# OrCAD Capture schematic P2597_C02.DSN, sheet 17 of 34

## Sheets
17 17_DSI Connector: size Custom
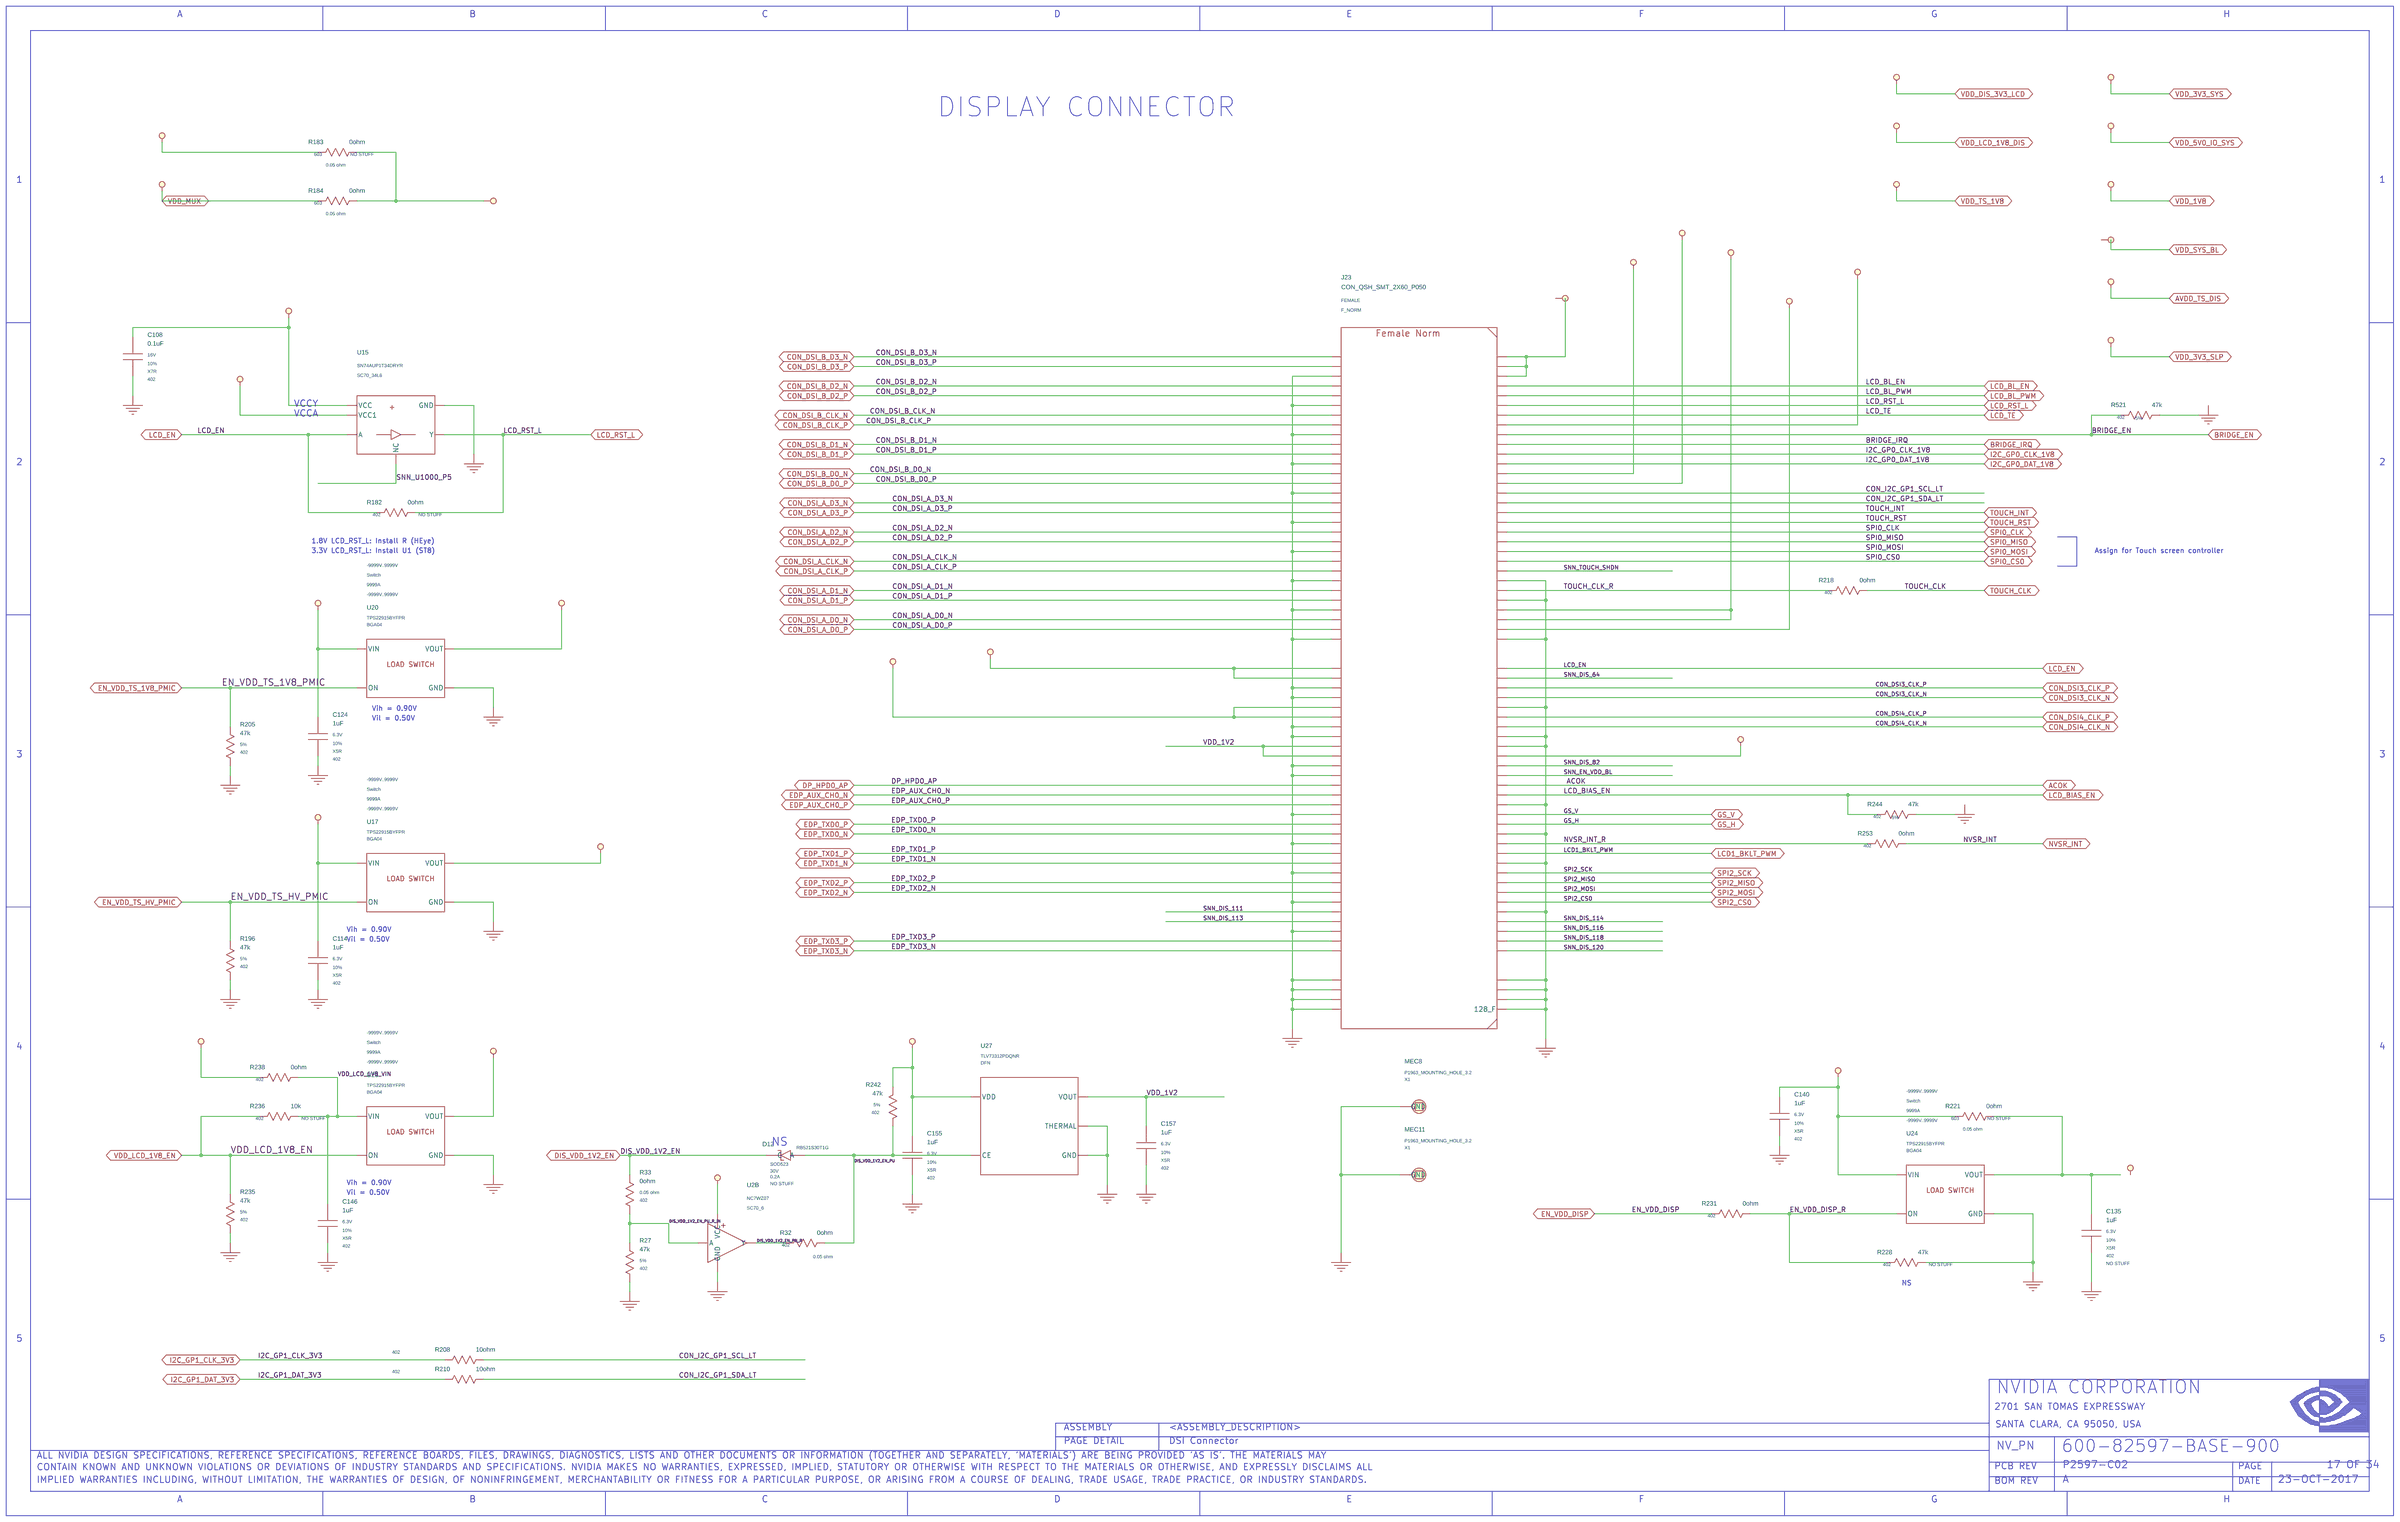
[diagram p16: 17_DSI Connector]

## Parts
sheet 17_DSI Connector
C108  0.1uF  [402]
C114  1uF  [402]
C124  1uF  [402]
C135  1uF  [402]
C140  1uF  [402]
C146  1uF  [402]
C155  1uF  [402]
C157  1uF  [402]
D12  D_SCHOTTKY  [DIODE_SMD_SOD523_B]
J23  CON_B2B_120  [CON_QSH_120_SMT_ST_P005]
MEC8  MOUNTING_HOLE  [MEC_HOLE_PTH_599C_INT422C_B701C320P]
MEC11  MOUNTING_HOLE  [MEC_HOLE_PTH_599C_INT422C_B701C320P]
R27  47k  [402]
R32  0ohm  [402]
R33  0ohm  [402]
R182  0ohm  [402]
R183  0ohm  [603]
R184  0ohm  [603]
R196  47k  [402]
R205  47k  [402]
R208  10ohm  [402]
R210  10ohm  [402]
R218  0ohm  [402]
R221  0ohm  [603]
R228  47k  [402]
R231  0ohm  [402]
R235  47k  [402]
R236  10k  [402]
R238  0ohm  [402]
R242  47k  [402]
R244  47k  [402]
R253  0ohm  [402]
R521  47k  [402]
U15  U_BUF_FXLP34  [DFN06_P050_015X010_C]
U17  U_SW_LOAD  [BGA_0004_P040_008X008]
U20  U_SW_LOAD  [BGA_0004_P040_008X008]
U24  U_SW_LOAD  [BGA_0004_P040_008X008]
U26  U_SW_LOAD  [BGA_0004_P040_008X008]
U27  0mV  [DFN04_P065_010X010_T005X005]
sheet 22_FAN AND DEBUG
U2  U_BUF_OD  [SC70_6]  (sections A,B)

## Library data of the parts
C108 = C: ASSEMBLY: DISPLAY; CDS_LIB: discrete; CDS_PART_NAME: C_0402-0.1UF,X7R,10%,16V,036-0014-000; CDS_PHYS_PART_NAME: C_0402-0.1UF,X7R,10%,16V,036-0014-000-0.1UF,036-0014-000; CDS_SEC: 1; DEVICE_TYPENAME: C_0402-01UFX7R1016V036-0014-000-01UF036-0014-000; DRAWING: @P2597_C02_LIB.P2597_C02(SCH_1):PAGE17; MAT: X7R; MAX_VOLTAGE: 16V; NV_PN: 036-0014-000; PATH: I301; PHYS_PAGE: 17; ROT: 0; SEC: 1; SIGNAL_MODEL: nv_cap; TOL: 10%; VER: 1; XY: (-11500,5800)
C114 = C: ASSEMBLY: DISPLAY; CDS_LIB: discrete; CDS_PART_NAME: C_0402-1UF,X5R,10%,6.3V,039-0008-000; CDS_PHYS_PART_NAME: C_0402-1UF,X5R,10%,6.3V,039-0008-000-039-0008-000,1UF; CDS_SEC: 1; DEVICE_TYPENAME: C_0402-1UFX5R1063V039-0008-000-039-0008-0001UF; DRAWING: @P2597_C02_LIB.P2597_C02(SCH_1):PAGE17; MAT: X5R; MAX_VOLTAGE: 6.3V; NV_PN: 039-0008-000; PATH: I336; PHYS_PAGE: 17; ROT: 0; SEC: 1; SIGNAL_MODEL: DEFAULT_CAPACITOR_1e+06pF_2_1; TOL: 10%; VER: 1; XY: (-10550,2700)
C124 = C: ASSEMBLY: DISPLAY; CDS_LIB: discrete; CDS_PART_NAME: C_0402-1UF,X5R,10%,6.3V,039-0008-000; CDS_PHYS_PART_NAME: C_0402-1UF,X5R,10%,6.3V,039-0008-000-039-0008-000,1UF; CDS_SEC: 1; DEVICE_TYPENAME: C_0402-1UFX5R1063V039-0008-000-039-0008-0001UF; DRAWING: @P2597_C02_LIB.P2597_C02(SCH_1):PAGE17; MAT: X5R; MAX_VOLTAGE: 6.3V; NV_PN: 039-0008-000; PATH: I338; PHYS_PAGE: 17; ROT: 0; SEC: 1; SIGNAL_MODEL: DEFAULT_CAPACITOR_1e+06pF_2_1; TOL: 10%; VER: 1; XY: (-10550,3850)
C135 = C: ASSEMBLY: DISPLAY; CDS_LIB: discrete; CDS_PART_NAME: C_0402-1UF,X5R,10%,6.3V,039-0008-000; CDS_PHYS_PART_NAME: C_0402-1UF,X5R,10%,6.3V,039-0008-000-039-0008-000,1UF; CDS_SEC: 1; DEVICE_TYPENAME: C_0402-1UFX5R1063V039-0008-000-039-0008-0001UF; DRAWING: @P2597_C02_LIB.P2597_C02(SCH_1):PAGE17; MAT: X5R; MAX_VOLTAGE: 6.3V; NV_PN: 039-0008-000; PATH: I233; PHYS_PAGE: 17; ROT: 0; SEC: 1; SIGNAL_MODEL: DEFAULT_CAPACITOR_1e+06pF_2_1; SKU: NO STUFF; TOL: 10%; VER: 1; XY: (-1450,1300)
C140 = C: ASSEMBLY: DISPLAY; CDS_LIB: discrete; CDS_PART_NAME: C_0402-1UF,X5R,10%,6.3V,039-0008-000; CDS_PHYS_PART_NAME: C_0402-1UF,X5R,10%,6.3V,039-0008-000-039-0008-000,1UF; CDS_SEC: 1; DEVICE_TYPENAME: C_0402-1UFX5R1063V039-0008-000-039-0008-0001UF; DRAWING: @P2597_C02_LIB.P2597_C02(SCH_1):PAGE17; MAT: X5R; MAX_VOLTAGE: 6.3V; NV_PN: 039-0008-000; PATH: I234; PHYS_PAGE: 17; ROT: 0; SEC: 1; SIGNAL_MODEL: DEFAULT_CAPACITOR_1e+06pF_2_1; TOL: 10%; VER: 1; XY: (-3050,1900)
C146 = C: ASSEMBLY: DISPLAY; CDS_LIB: discrete; CDS_PART_NAME: C_0402-1UF,X5R,10%,6.3V,039-0008-000; CDS_PHYS_PART_NAME: C_0402-1UF,X5R,10%,6.3V,039-0008-000-039-0008-000,1UF; CDS_SEC: 1; DEVICE_TYPENAME: C_0402-1UFX5R1063V039-0008-000-039-0008-0001UF; DRAWING: @P2597_C02_LIB.P2597_C02(SCH_1):PAGE17; MAT: X5R; MAX_VOLTAGE: 6.3V; NV_PN: 039-0008-000; PATH: I333; PHYS_PAGE: 17; ROT: 0; SEC: 1; SIGNAL_MODEL: DEFAULT_CAPACITOR_1e+06pF_2_1; TOL: 10%; VER: 1; XY: (-10500,1350)
C155 = C: ASSEMBLY: DISPLAY; CDS_LIB: discrete; CDS_PART_NAME: C_0402-1UF,X5R,10%,6.3V,039-0008-000; CDS_PHYS_PART_NAME: C_0402-1UF,X5R,10%,6.3V,039-0008-000-039-0008-000,1UF; CDS_SEC: 1; DEVICE_TYPENAME: C_0402-1UFX5R1063V039-0008-000-039-0008-0001UF; DRAWING: @P2597_C02_LIB.P2597_C02(SCH_1):PAGE17; MAT: X5R; MAX_VOLTAGE: 6.3V; NV_PN: 039-0008-000; PATH: I320; PHYS_PAGE: 17; ROT: 0; SEC: 1; SIGNAL_MODEL: nv_cap; TOL: 10%; VER: 1; XY: (-7500,1700)
C157 = C: ASSEMBLY: DISPLAY; CDS_LIB: discrete; CDS_PART_NAME: C_0402-1UF,X5R,10%,6.3V,039-0008-000; CDS_PHYS_PART_NAME: C_0402-1UF,X5R,10%,6.3V,039-0008-000-039-0008-000,1UF; CDS_SEC: 1; DEVICE_TYPENAME: C_0402-1UFX5R1063V039-0008-000-039-0008-0001UF; DRAWING: @P2597_C02_LIB.P2597_C02(SCH_1):PAGE17; MAT: X5R; MAX_VOLTAGE: 6.3V; NV_PN: 039-0008-000; PATH: I325; PHYS_PAGE: 17; ROT: 0; SEC: 1; SIGNAL_MODEL: nv_cap; TOL: 10%; VER: 1; XY: (-6300,1750)
D12 = D_SCHOTTKY: ASSEMBLY: DISPLAY; CDS_LIB: discrete; CDS_PART_NAME: D_SCHOTTKY_SOD523-RB521S30T1G,SINGLE,30V,1A,0.5V@0.2A,0.2A,090-0102-000; CDS_PHYS_PART_NAME: D_SCHOTTKY_SOD523-RB521S30T1G,SINGLE,30V,1A,0.5V@0.2A,0.2A,090-0102-000-090-0102-000; CDS_SEC: 1; CONFIGURATION: Single; CONTINUOUS_CURRENT: 0.2A; DEVICE_TYPENAME: D_SCHOTTKY_SOD523-RB521S30T1GSINGLE30V1A05V02A02A090-0102-000-090-0102-000; DRAWING: @P2597_C02_LIB.P2597_C02(SCH_1):PAGE17; FORWARD_VOLTAGE: 0.5V@0.2A; MAX_CURRENT: 1A; MAX_VOLTAGE: 30V; NV_NAME: RB521S30T1G; NV_PN: 090-0102-000; PACK_TYPE: SOD523; PATH: I339; PHYS_PAGE: 17; ROT: 0; SEC: 1; SEC_TYPE: SOD523; SKU: NO STUFF; VER: 1; XY: (-8150,1700)
J23 = CON_B2B_120: ANGLE: 0; ASSEMBLY: DISPLAY; CDS_LIB: electro_mechanic; CDS_PART_NAME: CON_B2B_120_F_NORM-CON_QSH_SMT_2X60_P050,FEMALE,0.5MM,0,YES,YES,NO,NO,NO,NA,NA,080-1346-000; CDS_PHYS_PART_NAME: CON_B2B_120_F_NORM-CON_QSH_SMT_2X60_P050,FEMALE,0.5MM,0,YES,YES,NO,NO,NO,NA,NA,080-1346-000-080-1346-000; CDS_SEC: 1; DEVICE_TYPENAME: CON_B2B_120_F_NORM-CON_QSH_SMT_2X60_P050FEMALE05MM0YESYESNONONONANA080-1346-000-080-1346-000; DRAWING: @P2597_C02_LIB.P2597_C02(SCH_1):PAGE17; EMI_GROUND_TAB: NO; GENDER: FEMALE; LATCHING: NO; MAX_CURRENT: NA; MAX_VOLTAGE: NA; NV_NAME: CON_QSH_SMT_2X60_P050; NV_PN: 080-1346-000; PACK_TYPE: F_NORM; PATH: I274; PHYS_PAGE: 17; PITCH: 0.5MM; REFLOW: YES; ROT: 0; SEC: 1; SEC_TYPE: F_NORM; SHIELDED: NO; SHROUDED: YES; VER: 1; XY: (-4900,4150)
MEC8 = MOUNTING_HOLE: CDS_LIB: mechanic; CDS_PART_NAME: MOUNTING_HOLE_X1-P1963_MOUNTING_HOLE_3.2; CDS_PHYS_PART_NAME: MOUNTING_HOLE_X1-P1963_MOUNTING_HOLE_3.2; CDS_SEC: 1; DEVICE_TYPENAME: MOUNTING_HOLE_X1-P1963_MOUNTING_HOLE_32; DRAWING: @P2597_C02_LIB.P2597_C02(SCH_1):PAGE17; NV_NAME: P1963_MOUNTING_HOLE_3.2; PACK_TYPE: X1; PATH: I309; PHYS_PAGE: 17; ROT: 0; SEC: 1; SEC_TYPE: X1; VER: 1; XY: (-4900,1950)
MEC11 = MOUNTING_HOLE: CDS_LIB: mechanic; CDS_PART_NAME: MOUNTING_HOLE_X1-P1963_MOUNTING_HOLE_3.2; CDS_PHYS_PART_NAME: MOUNTING_HOLE_X1-P1963_MOUNTING_HOLE_3.2; CDS_SEC: 1; DEVICE_TYPENAME: MOUNTING_HOLE_X1-P1963_MOUNTING_HOLE_32; DRAWING: @P2597_C02_LIB.P2597_C02(SCH_1):PAGE17; NV_NAME: P1963_MOUNTING_HOLE_3.2; PACK_TYPE: X1; PATH: I311; PHYS_PAGE: 17; ROT: 0; SEC: 1; SEC_TYPE: X1; VER: 1; XY: (-4900,1600)
R27 = R#1: ASSEMBLY: DISPLAY; CDS_LIB: discrete; CDS_PART_NAME: R_0402-47K,5 %,62.5MW,195-0599-000; CDS_PHYS_PART_NAME: R_0402-47K,5 %,62.5MW,195-0599-000-195-0599-000,47K; CDS_SEC: 1; CHIPS_PART_NAME: R; DEVICE_TYPENAME: R_0402-47K5625MW195-0599-000-195-0599-00047K; DRAWING: @P2597_C02_LIB.P2597_C02(SCH_1):PAGE17; MAX_WATTAGE: 62.5mW; NV_PN: 195-0599-000; PATH: I352; PHYS_PAGE: 17; ROT: 0; SEC: 1; SIGNAL_MODEL: nv_res; TOL: 5%; VER: 2; XY: (-8950,1150)
R32 = R: ASSEMBLY: DISPLAY; CDS_LIB: discrete; CDS_PART_NAME: R_0402-0OHM,0.05 OHM,62.5MW,195-2655-000; CDS_PHYS_PART_NAME: R_0402-0OHM,0.05 OHM,62.5MW,195-2655-000-0OHM,195-2655-000; CDS_SEC: 1; DEVICE_TYPENAME: R_0402-0OHM005OHM625MW195-2655-000-0OHM195-2655-000; DRAWING: @P2597_C02_LIB.P2597_C02(SCH_1):PAGE17; MAX_WATTAGE: 62.5mW; NV_PN: 195-2655-000; PATH: I359; PHYS_PAGE: 17; ROT: 0; SEC: 1; SIGNAL_MODEL: nv_res; TOL: 0.05 ohm; VER: 1; XY: (-8050,1250)
R33 = R#1: ASSEMBLY: DISPLAY; CDS_LIB: discrete; CDS_PART_NAME: R_0402-0OHM,0.05 OHM,62.5MW,195-2655-000; CDS_PHYS_PART_NAME: R_0402-0OHM,0.05 OHM,62.5MW,195-2655-000-0OHM,195-2655-000; CDS_SEC: 1; CHIPS_PART_NAME: R; DEVICE_TYPENAME: R_0402-0OHM005OHM625MW195-2655-000-0OHM195-2655-000; DRAWING: @P2597_C02_LIB.P2597_C02(SCH_1):PAGE17; MAX_WATTAGE: 62.5mW; NV_PN: 195-2655-000; PATH: I358; PHYS_PAGE: 17; ROT: 0; SEC: 1; SIGNAL_MODEL: nv_res; TOL: 0.05 ohm; VER: 2; XY: (-8950,1500)
R182 = R: ASSEMBLY: DISPLAY; CDS_LIB: discrete; CDS_PART_NAME: R_0402-0OHM,0.05 OHM,62.5MW,195-2655-000; CDS_PHYS_PART_NAME: R_0402-0OHM,0.05 OHM,62.5MW,195-2655-000-0OHM,195-2655-000; CDS_SEC: 1; DEVICE_TYPENAME: R_0402-0OHM005OHM625MW195-2655-000-0OHM195-2655-000; DRAWING: @P2597_C02_LIB.P2597_C02(SCH_1):PAGE17; MAX_WATTAGE: 62.5mW; NV_PN: 195-2655-000; PATH: I300; PHYS_PAGE: 17; ROT: 0; SEC: 1; SIGNAL_MODEL: nv_res; SKU: NO STUFF; TOL: 0.05 ohm; VER: 1; XY: (-10150,5000)
R183 = R: ASSEMBLY: DISPLAY; CDS_LIB: discrete; CDS_PART_NAME: R_0603-0OHM,0.05 OHM,0.1W,195-2656-000; CDS_PHYS_PART_NAME: R_0603-0OHM,0.05 OHM,0.1W,195-2656-000-0OHM,195-2656-000; CDS_SEC: 1; DEVICE_TYPENAME: R_0603-0OHM005OHM01W195-2656-000-0OHM195-2656-000; DRAWING: @P2597_C02_LIB.P2597_C02(SCH_1):PAGE17; MAX_WATTAGE: 0.1W; NV_PN: 195-2656-000; PATH: I137; PHYS_PAGE: 17; ROT: 0; SEC: 1; SIGNAL_MODEL: nv_res; SKU: NO STUFF; TOL: 0.05 ohm; VER: 1; XY: (-10450,6850)
R184 = R: ASSEMBLY: DISPLAY; CDS_LIB: discrete; CDS_PART_NAME: R_0603-0OHM,0.05 OHM,0.1W,195-2656-000; CDS_PHYS_PART_NAME: R_0603-0OHM,0.05 OHM,0.1W,195-2656-000-0OHM,195-2656-000; CDS_SEC: 1; DEVICE_TYPENAME: R_0603-0OHM005OHM01W195-2656-000-0OHM195-2656-000; DRAWING: @P2597_C02_LIB.P2597_C02(SCH_1):PAGE17; MAX_WATTAGE: 0.1W; NV_PN: 195-2656-000; PATH: I136; PHYS_PAGE: 17; ROT: 0; SEC: 1; SIGNAL_MODEL: nv_res; TOL: 0.05 ohm; VER: 1; XY: (-10450,6600)
R196 = R#1: ASSEMBLY: DISPLAY; CDS_LIB: discrete; CDS_PART_NAME: R_0402-47K,5 %,62.5MW,195-0599-000; CDS_PHYS_PART_NAME: R_0402-47K,5 %,62.5MW,195-0599-000-195-0599-000,47K; CDS_SEC: 1; CHIPS_PART_NAME: R; DEVICE_TYPENAME: R_0402-47K5625MW195-0599-000-195-0599-00047K; DRAWING: @P2597_C02_LIB.P2597_C02(SCH_1):PAGE17; MAX_WATTAGE: 62.5mW; NV_PN: 195-0599-000; PATH: I349; PHYS_PAGE: 17; ROT: 0; SEC: 1; SIGNAL_MODEL: nv_res; TOL: 5%; VER: 2; XY: (-11000,2700)
R205 = R#1: ASSEMBLY: DISPLAY; CDS_LIB: discrete; CDS_PART_NAME: R_0402-47K,5 %,62.5MW,195-0599-000; CDS_PHYS_PART_NAME: R_0402-47K,5 %,62.5MW,195-0599-000-195-0599-000,47K; CDS_SEC: 1; CHIPS_PART_NAME: R; DEVICE_TYPENAME: R_0402-47K5625MW195-0599-000-195-0599-00047K; DRAWING: @P2597_C02_LIB.P2597_C02(SCH_1):PAGE17; MAX_WATTAGE: 62.5mW; NV_PN: 195-0599-000; PATH: I347; PHYS_PAGE: 17; ROT: 0; SEC: 1; SIGNAL_MODEL: nv_res; TOL: 5%; VER: 2; XY: (-11000,3800)
R208 = R: ASSEMBLY: DISPLAY; CDS_LIB: discrete; CDS_PART_NAME: R_0402-10OHM,1 %,62.5MW,195-0001-000; CDS_PHYS_PART_NAME: R_0402-10OHM,1 %,62.5MW,195-0001-000-10OHM,195-0001-000; CDS_SEC: 1; DEVICE_TYPENAME: R_0402-10OHM1625MW195-0001-000-10OHM195-0001-000; DRAWING: @P2597_C02_LIB.P2597_C02(SCH_1):PAGE17; MAX_WATTAGE: 62.5mW; NV_PN: 195-0001-000; PATH: I146; PHYS_PAGE: 17; ROT: 0; SEC: 1; SIGNAL_MODEL: nv_res; TOL: 1%; VER: 1; XY: (-9800,650)
R210 = R: ASSEMBLY: DISPLAY; CDS_LIB: discrete; CDS_PART_NAME: R_0402-10OHM,1 %,62.5MW,195-0001-000; CDS_PHYS_PART_NAME: R_0402-10OHM,1 %,62.5MW,195-0001-000-10OHM,195-0001-000; CDS_SEC: 1; DEVICE_TYPENAME: R_0402-10OHM1625MW195-0001-000-10OHM195-0001-000; DRAWING: @P2597_C02_LIB.P2597_C02(SCH_1):PAGE17; MAX_WATTAGE: 62.5mW; NV_PN: 195-0001-000; PATH: I145; PHYS_PAGE: 17; ROT: 0; SEC: 1; SIGNAL_MODEL: nv_res; TOL: 1%; VER: 1; XY: (-9800,550)
R218 = R: ASSEMBLY: DISPLAY; CDS_LIB: discrete; CDS_PART_NAME: R_0402-0OHM,0.05 OHM,62.5MW,195-2655-000; CDS_PHYS_PART_NAME: R_0402-0OHM,0.05 OHM,62.5MW,195-2655-000-0OHM,195-2655-000; CDS_SEC: 1; DEVICE_TYPENAME: R_0402-0OHM005OHM625MW195-2655-000-0OHM195-2655-000; DRAWING: @P2597_C02_LIB.P2597_C02(SCH_1):PAGE17; MAX_WATTAGE: 62.5mW; NV_PN: 195-2655-000; PATH: I221; PHYS_PAGE: 17; ROT: 0; SEC: 1; SIGNAL_MODEL: nv_res; TOL: 0.05 ohm; VER: 1; XY: (-2700,4600)
R221 = R: ASSEMBLY: DISPLAY; CDS_LIB: discrete; CDS_PART_NAME: R_0603-0OHM,0.05 OHM,0.1W,195-2656-000; CDS_PHYS_PART_NAME: R_0603-0OHM,0.05 OHM,0.1W,195-2656-000-0OHM,195-2656-000; CDS_SEC: 1; DEVICE_TYPENAME: R_0603-0OHM005OHM01W195-2656-000-0OHM195-2656-000; DRAWING: @P2597_C02_LIB.P2597_C02(SCH_1):PAGE17; MAX_WATTAGE: 0.1W; NV_PN: 195-2656-000; PATH: I153; PHYS_PAGE: 17; ROT: 0; SEC: 1; SIGNAL_MODEL: nv_res; SKU: NO STUFF; TOL: 0.05 ohm; VER: 1; XY: (-2050,1900)
R228 = R: ASSEMBLY: DISPLAY; CDS_LIB: discrete; CDS_PART_NAME: R_0402-47K,5 %,62.5MW,195-0599-000; CDS_PHYS_PART_NAME: R_0402-47K,5 %,62.5MW,195-0599-000-195-0599-000,47K; CDS_SEC: 1; DEVICE_TYPENAME: R_0402-47K5625MW195-0599-000-195-0599-00047K; DRAWING: @P2597_C02_LIB.P2597_C02(SCH_1):PAGE17; MAX_WATTAGE: 62.5mW; NV_PN: 195-0599-000; PATH: I231; PHYS_PAGE: 17; ROT: 0; SEC: 1; SIGNAL_MODEL: nv_res; SKU: NO STUFF; TOL: 5%; VER: 1; XY: (-2400,1150)
R231 = R: ASSEMBLY: DISPLAY; CDS_LIB: discrete; CDS_PART_NAME: R_0402-0OHM,0.05 OHM,62.5MW,195-2655-000; CDS_PHYS_PART_NAME: R_0402-0OHM,0.05 OHM,62.5MW,195-2655-000-0OHM,195-2655-000; CDS_SEC: 1; DEVICE_TYPENAME: R_0402-0OHM005OHM625MW195-2655-000-0OHM195-2655-000; DRAWING: @P2597_C02_LIB.P2597_C02(SCH_1):PAGE17; MAX_WATTAGE: 62.5mW; NV_PN: 195-2655-000; PATH: I230; PHYS_PAGE: 17; ROT: 0; SEC: 1; SIGNAL_MODEL: nv_res; TOL: 0.05 ohm; VER: 1; XY: (-3300,1400)
R235 = R#1: ASSEMBLY: DISPLAY; CDS_LIB: discrete; CDS_PART_NAME: R_0402-47K,5 %,62.5MW,195-0599-000; CDS_PHYS_PART_NAME: R_0402-47K,5 %,62.5MW,195-0599-000-195-0599-000,47K; CDS_SEC: 1; CHIPS_PART_NAME: R; DEVICE_TYPENAME: R_0402-47K5625MW195-0599-000-195-0599-00047K; DRAWING: @P2597_C02_LIB.P2597_C02(SCH_1):PAGE17; MAX_WATTAGE: 62.5mW; NV_PN: 195-0599-000; PATH: I351; PHYS_PAGE: 17; ROT: 0; SEC: 1; SIGNAL_MODEL: nv_res; TOL: 5%; VER: 2; XY: (-11000,1400)
R236 = R: ASSEMBLY: DISPLAY; CDS_LIB: discrete; CDS_PART_NAME: R_0402-10K,5 %,62.5MW,195-0486-000; CDS_PHYS_PART_NAME: R_0402-10K,5 %,62.5MW,195-0486-000-10K,195-0486-000; CDS_SEC: 1; DEVICE_TYPENAME: R_0402-10K5625MW195-0486-000-10K195-0486-000; DRAWING: @P2597_C02_LIB.P2597_C02(SCH_1):PAGE17; MAX_WATTAGE: 62.5mW; NV_PN: 195-0486-000; PATH: I252; PHYS_PAGE: 17; ROT: 0; SEC: 1; SIGNAL_MODEL: nv_res; SKU: NO STUFF; TOL: 5%; VER: 1; XY: (-10750,1900)
R238 = R: ASSEMBLY: DISPLAY; CDS_LIB: discrete; CDS_PART_NAME: R_0402-0OHM,0.05 OHM,62.5MW,195-2655-000; CDS_PHYS_PART_NAME: R_0402-0OHM,0.05 OHM,62.5MW,195-2655-000-0OHM,195-2655-000; CDS_SEC: 1; DEVICE_TYPENAME: R_0402-0OHM005OHM625MW195-2655-000-0OHM195-2655-000; DRAWING: @P2597_C02_LIB.P2597_C02(SCH_1):PAGE17; MAX_WATTAGE: 62.5mW; NV_PN: 195-2655-000; PATH: I251; PHYS_PAGE: 17; ROT: 0; SEC: 1; SIGNAL_MODEL: nv_res; TOL: 0.05 ohm; VER: 1; XY: (-10750,2100)
R242 = R#1: ASSEMBLY: DISPLAY; CDS_LIB: discrete; CDS_PART_NAME: R_0402-47K,5 %,62.5MW,195-0599-000; CDS_PHYS_PART_NAME: R_0402-47K,5 %,62.5MW,195-0599-000-195-0599-000,47K; CDS_SEC: 1; CHIPS_PART_NAME: R; DEVICE_TYPENAME: R_0402-47K5625MW195-0599-000-195-0599-00047K; DRAWING: @P2597_C02_LIB.P2597_C02(SCH_1):PAGE17; MAX_WATTAGE: 62.5mW; NV_PN: 195-0599-000; PATH: I340; PHYS_PAGE: 17; ROT: 2; SEC: 1; SIGNAL_MODEL: nv_res; TOL: 5%; VER: 2; XY: (-7600,1950)
R244 = R: ASSEMBLY: DISPLAY; CDS_LIB: discrete; CDS_PART_NAME: R_0402-47K,5 %,62.5MW,195-0599-000; CDS_PHYS_PART_NAME: R_0402-47K,5 %,62.5MW,195-0599-000-195-0599-000,47K; CDS_SEC: 1; DEVICE_TYPENAME: R_0402-47K5625MW195-0599-000-195-0599-00047K; DRAWING: @P2597_C02_LIB.P2597_C02(SCH_1):PAGE17; MAX_WATTAGE: 62.5mW; NV_PN: 195-0599-000; PATH: I342; PHYS_PAGE: 17; ROT: 0; SEC: 1; SIGNAL_MODEL: nv_res; TOL: 5%; VER: 1; XY: (-2450,3450)
R253 = R: ASSEMBLY: DISPLAY; CDS_LIB: discrete; CDS_PART_NAME: R_0402-0OHM,0.05 OHM,62.5MW,195-2655-000; CDS_PHYS_PART_NAME: R_0402-0OHM,0.05 OHM,62.5MW,195-2655-000-0OHM,195-2655-000; CDS_SEC: 1; DEVICE_TYPENAME: R_0402-0OHM005OHM625MW195-2655-000-0OHM195-2655-000; DRAWING: @P2597_C02_LIB.P2597_C02(SCH_1):PAGE17; MAX_WATTAGE: 62.5mW; NV_PN: 195-2655-000; PATH: I326; PHYS_PAGE: 17; ROT: 0; SEC: 1; SIGNAL_MODEL: nv_res; TOL: 0.05 ohm; VER: 1; XY: (-2500,3300)
R521 = R: ASSEMBLY: DISPLAY; CDS_LIB: discrete; CDS_PART_NAME: R_0402-47K,5 %,62.5MW,195-0599-000; CDS_PHYS_PART_NAME: R_0402-47K,5 %,62.5MW,195-0599-000-195-0599-000,47K; CDS_SEC: 1; DEVICE_TYPENAME: R_0402-47K5625MW195-0599-000-195-0599-00047K; DRAWING: @P2597_C02_LIB.P2597_C02(SCH_1):PAGE17; MAX_WATTAGE: 62.5mW; NV_PN: 195-0599-000; PATH: I345; PHYS_PAGE: 17; ROT: 0; SEC: 1; SIGNAL_MODEL: nv_res; TOL: 5%; VER: 1; XY: (-1200,5500)
U15 = U_BUF_FXLP34: ASSEMBLY: DISPLAY; CDS_LIB: logic; CDS_PART_NAME: U_BUF_FXLP34_SC70_34L6-SN74AUP1T34DRYR,TRANSLATOR,115-1283-000; CDS_PHYS_PART_NAME: U_BUF_FXLP34_SC70_34L6-SN74AUP1T34DRYR,TRANSLATOR,115-1283-000-115-1283-000; CDS_SEC: 1; DEVICE_TYPENAME: U_BUF_FXLP34_SC70_34L6-SN74AUP1T34DRYRTRANSLATOR115-1283-000-115-1283-000; DRAWING: @P2597_C02_LIB.P2597_C02(SCH_1):PAGE17; FUNCTION: Translator; NV_NAME: SN74AUP1T34DRYR; NV_PN: 115-1283-000; PACK_TYPE: SC70_34L6; PATH: I306; PHYS_PAGE: 17; ROT: 0; SEC: 1; SEC_TYPE: SC70_34L6; VER: 1; XY: (-10150,5450)
U17 = U_SW_LOAD: ASSEMBLY: DISPLAY; CDS_LIB: analog; CDS_PART_NAME: U_SW_LOAD_BGA04-TPS22915BYFPR,-9999V..9999V,-9999V..9999V,9999A,SWITCH,115-1834-000; CDS_PHYS_PART_NAME: U_SW_LOAD_BGA04-TPS22915BYFPR,-9999V..9999V,-9999V..9999V,9999A,SWITCH,115-1834-000-115-1834-000; CDS_SEC: 1; DEVICE_TYPENAME: U_SW_LOAD_BGA04-TPS22915BYFPR-9999V9999V-9999V9999V9999ASWITCH115-1834-000-115-1834-000; DRAWING: @P2597_C02_LIB.P2597_C02(SCH_1):PAGE17; MAX_CURRENT: 9999A; MAX_VOLTAGE: -9999V..9999V; NV_NAME: TPS22915BYFPR; NV_PN: 115-1834-000; OUTPUT_VOLTAGE: -9999V..9999V; PACK_TYPE: BGA04; PATH: I243; PHYS_PAGE: 17; ROT: 0; SEC: 1; SEC_TYPE: BGA04; TYPE: Switch; VER: 3; XY: (-10100,3100)
U20 = U_SW_LOAD: ASSEMBLY: DISPLAY; CDS_LIB: analog; CDS_PART_NAME: U_SW_LOAD_BGA04-TPS22915BYFPR,-9999V..9999V,-9999V..9999V,9999A,SWITCH,115-1834-000; CDS_PHYS_PART_NAME: U_SW_LOAD_BGA04-TPS22915BYFPR,-9999V..9999V,-9999V..9999V,9999A,SWITCH,115-1834-000-115-1834-000; CDS_SEC: 1; DEVICE_TYPENAME: U_SW_LOAD_BGA04-TPS22915BYFPR-9999V9999V-9999V9999V9999ASWITCH115-1834-000-115-1834-000; DRAWING: @P2597_C02_LIB.P2597_C02(SCH_1):PAGE17; MAX_CURRENT: 9999A; MAX_VOLTAGE: -9999V..9999V; NV_NAME: TPS22915BYFPR; NV_PN: 115-1834-000; OUTPUT_VOLTAGE: -9999V..9999V; PACK_TYPE: BGA04; PATH: I238; PHYS_PAGE: 17; ROT: 0; SEC: 1; SEC_TYPE: BGA04; TYPE: Switch; VER: 3; XY: (-10100,4200)
U24 = U_SW_LOAD: ASSEMBLY: DISPLAY; CDS_LIB: analog; CDS_PART_NAME: U_SW_LOAD_BGA04-TPS22915BYFPR,-9999V..9999V,-9999V..9999V,9999A,SWITCH,115-1834-000; CDS_PHYS_PART_NAME: U_SW_LOAD_BGA04-TPS22915BYFPR,-9999V..9999V,-9999V..9999V,9999A,SWITCH,115-1834-000-115-1834-000; CDS_SEC: 1; DEVICE_TYPENAME: U_SW_LOAD_BGA04-TPS22915BYFPR-9999V9999V-9999V9999V9999ASWITCH115-1834-000-115-1834-000; DRAWING: @P2597_C02_LIB.P2597_C02(SCH_1):PAGE17; MAX_CURRENT: 9999A; MAX_VOLTAGE: -9999V..9999V; NV_NAME: TPS22915BYFPR; NV_PN: 115-1834-000; OUTPUT_VOLTAGE: -9999V..9999V; PACK_TYPE: BGA04; PATH: I255; PHYS_PAGE: 17; ROT: 0; SEC: 1; SEC_TYPE: BGA04; TYPE: Switch; VER: 3; XY: (-2200,1500)
U26 = U_SW_LOAD: ASSEMBLY: DISPLAY; CDS_LIB: analog; CDS_PART_NAME: U_SW_LOAD_BGA04-TPS22915BYFPR,-9999V..9999V,-9999V..9999V,9999A,SWITCH,115-1834-000; CDS_PHYS_PART_NAME: U_SW_LOAD_BGA04-TPS22915BYFPR,-9999V..9999V,-9999V..9999V,9999A,SWITCH,115-1834-000-115-1834-000; CDS_SEC: 1; DEVICE_TYPENAME: U_SW_LOAD_BGA04-TPS22915BYFPR-9999V9999V-9999V9999V9999ASWITCH115-1834-000-115-1834-000; DRAWING: @P2597_C02_LIB.P2597_C02(SCH_1):PAGE17; MAX_CURRENT: 9999A; MAX_VOLTAGE: -9999V..9999V; NV_NAME: TPS22915BYFPR; NV_PN: 115-1834-000; OUTPUT_VOLTAGE: -9999V..9999V; PACK_TYPE: BGA04; PATH: I247; PHYS_PAGE: 17; ROT: 0; SEC: 1; SEC_TYPE: BGA04; TYPE: Switch; VER: 3; XY: (-10100,1800)
U27 = U_VREG_RP114X: ASSEMBLY: DISPLAY; CDS_LIB: power_supply; CDS_PART_NAME: U_VREG_RP114X_DFN-TLV73312PDQNR,LOW DROP OUT/FIXED,0.45V@0.3A,1.2V..1.2V,1.4%,0MV,5.5V,0.3A,0.4W,315-0934-000; CDS_PHYS_PART_NAME: U_VREG_RP114X_DFN-TLV73312PDQNR,LOW DROP OUT/FIXED,0.45V@0.3A,1.2V..1.2V,1.4%,0MV,5.5V,0.3A,0.4W,315-0934-000-0MV,315-0934-000; CDS_SEC: 1; DEVICE_TYPENAME: U_VREG_RP114X_DFN-TLV73312PDQNRLOWDROPOUTFIXED045V03A12V12V140MV55V03A04W315-0934-000-0MV315-0934-000; DRAWING: @P2597_C02_LIB.P2597_C02(SCH_1):PAGE17; FORWARD_VOLTAGE: 0.45V@0.3A; MAX_CURRENT: 0.3A; MAX_VOLTAGE: 5.5V; MAX_WATTAGE: 0.4W; NV_NAME: TLV73312PDQNR; NV_PN: 315-0934-000; OUTPUT_VOLTAGE: 1.2V..1.2V; PACK_TYPE: DFN; PATH: I341; PHYS_PAGE: 17; ROT: 0; SEC: 1; SEC_TYPE: DFN; TOL: 1.40%; TYPE: Low Drop Out/Fixed; VER: 1; XY: (-6900,1850)
U2 = U_BUF_OD: ASSEMBLY: PM342; CDS_LIB: logic; CDS_PART_NAME: U_BUF_OD_SC70_6-NC7WZ07,BUFFER - OPEN DRAIN,115-1012-000; CDS_PHYS_PART_NAME: U_BUF_OD_SC70_6-NC7WZ07,BUFFER - OPEN DRAIN,115-1012-000-115-1012-000; CDS_SEC: 1; DEVICE_TYPENAME: U_BUF_OD_SC70_6-NC7WZ07BUFFER-OPENDRAIN115-1012-000-115-1012-000; DRAWING: @P2597_C02_LIB.P2597_C02(SCH_1):PAGE22; FUNCTION: Buffer - Open Drain; NV_NAME: NC7WZ07; NV_PN: 115-1012-000; PATH: I200; PHYS_PAGE: 22; ROT: 0; SEC: 1; VER: 1; XY: (-9850,5250)

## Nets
AVDD_TS_DIS: J23.26 U17.A1(VOUT)
GND: C108.2 C114.2 C124.2 C135.2 C140.2 C146.2 C155.2 C157.2 J23.5 J23.11 J23.17 J23.23 J23.29 J23.35 J23.41 J23.47 J23.48 J23.52 J23.53 J23.59 J23.60 J23.65 J23.67 J23.70 J23.73 J23.75 J23.76 J23.78 J23.81 J23.83 J23.90 J23.91 J23.96 J23.97 J23.102 J23.103 J23.109 J23.112 J23.115 J23.121 J23.122 J23.123 J23.124 J23.125 J23.126 J23.127 J23.128(128_F) MEC8.1(GND) MEC11.1(GND) R27.2 R196.2 R205.2 R228.2 R235.2 R244.2 R521.2 U2.2(GND) U15.3(GND) U17.B1(GND) U20.B1(GND) U24.B1(GND) U26.B1(GND) U27.2(GND) U27.5(THERMAL) ; also on sheet 1 2 3 4 5 6 7 9 10 11 12 13 14 15 16 18 19 20 21 22 23 24 25 26 30
VDD_1V2: C157.1 J23.77 J23.79 U27.1(VOUT)
VDD_1V8: C124.1 C155.1 J23.69 J23.71 R238.1 R242.1 U2.5(VCC) U15.1(VCC1) U20.A2(VIN) U27.4(VDD) ; also on sheet 4 5 9 10 12 13 16 18 19 20 22 24 30
VDD_3V3_SLP: C114.1 J23.16 U17.A2(VIN) ; also on sheet 4 5 11 16 20 21 22 25
VDD_3V3_SYS: C140.1 J23.61 J23.63 R221.1 U24.A2(VIN) ; also on sheet 1 2 3 4 5 6 12 13 18 19 23 24 25
VDD_5V0_IO_SYS: J23.80 R183.1 ; also on sheet 4 5 6 9 11 12 16 18 20 22 26 30
VDD_DIS_3V3_LCD: C108.1 C135.1 J23.54 J23.56 R221.2 U15.6(VCC) U24.A1(VOUT)
VDD_LCD_1V8_DIS: J23.58 U26.A1(VOUT)
VDD_LCD_1V8_EN: R235.1 R236.1 U26.B2(ON) ; also on sheet 13
VDD_LCD_1V8_VIN: C146.1 R236.2 R238.2 U26.A2(VIN)
VDD_MUX: R184.1 ; also on sheet 4 6 7
VDD_SYS_BL: J23.2 J23.4 J23.6 R183.2 R184.2
VDD_TS_1V8: J23.28 U20.A1(VOUT)
ACOK: J23.86 ; also on sheet 12 18 30
BRIDGE_EN: J23.18 R521.1 ; also on sheet 13
BRIDGE_IRQ: J23.20 ; also on sheet 13
CON_DSI3_CLK_N: J23.68 ; also on sheet 29
CON_DSI3_CLK_P: J23.66 ; also on sheet 29
CON_DSI4_CLK_N: J23.74 ; also on sheet 29
CON_DSI4_CLK_P: J23.72 ; also on sheet 29
CON_DSI_A_CLK_N: J23.43 ; also on sheet 29
CON_DSI_A_CLK_P: J23.45 ; also on sheet 29
CON_DSI_A_D0_N: J23.55 ; also on sheet 29
CON_DSI_A_D0_P: J23.57 ; also on sheet 29
CON_DSI_A_D1_N: J23.49 ; also on sheet 29
CON_DSI_A_D1_P: J23.51 ; also on sheet 29
CON_DSI_A_D2_N: J23.37 ; also on sheet 29
CON_DSI_A_D2_P: J23.39 ; also on sheet 29
CON_DSI_A_D3_N: J23.31 ; also on sheet 29
CON_DSI_A_D3_P: J23.33 ; also on sheet 29
CON_DSI_B_CLK_N: J23.13 ; also on sheet 29
CON_DSI_B_CLK_P: J23.15 ; also on sheet 29
CON_DSI_B_D0_N: J23.25 ; also on sheet 29
CON_DSI_B_D0_P: J23.27 ; also on sheet 29
CON_DSI_B_D1_N: J23.19 ; also on sheet 29
CON_DSI_B_D1_P: J23.21 ; also on sheet 29
CON_DSI_B_D2_N: J23.7 ; also on sheet 29
CON_DSI_B_D2_P: J23.9 ; also on sheet 29
CON_DSI_B_D3_N: J23.1 ; also on sheet 29
CON_DSI_B_D3_P: J23.3 ; also on sheet 29
CON_I2C_GP1_SCL_LT: J23.30 R208.2
CON_I2C_GP1_SDA_LT: J23.32 R210.2
DIS_VDD_1V2_EN: D12.1(C) R33.1 ; also on sheet 13
DIS_VDD_1V2_EN_PU: D12.2(A) R32.2 R242.2 U27.3(CE)
DIS_VDD_1V2_EN_PU_R: R32.1 U2.4(Y)
DIS_VDD_1V2_EN_PU_R_IN: R27.1 R33.2 U2.3(A)
DP_HPD0_AP: J23.85 ; also on sheet 29
EDP_AUX_CH0_N: J23.87 ; also on sheet 29
EDP_AUX_CH0_P: J23.89 ; also on sheet 29
EDP_TXD0_N: J23.95 ; also on sheet 29
EDP_TXD0_P: J23.93 ; also on sheet 29
EDP_TXD1_N: J23.101 ; also on sheet 29
EDP_TXD1_P: J23.99 ; also on sheet 29
EDP_TXD2_N: J23.107 ; also on sheet 29
EDP_TXD2_P: J23.105 ; also on sheet 29
EDP_TXD3_N: J23.119 ; also on sheet 29
EDP_TXD3_P: J23.117 ; also on sheet 29
EN_VDD_DISP: R231.1 ; also on sheet 13
EN_VDD_DISP_R: R228.1 R231.2 U24.B2(ON)
EN_VDD_TS_1V8_PMIC: R205.1 U20.B2(ON) ; also on sheet 13
EN_VDD_TS_HV_PMIC: R196.1 U17.B2(ON) ; also on sheet 13
GS_H: J23.94 ; also on sheet 29
GS_V: J23.92 ; also on sheet 29
I2C_GP0_CLK_1V8: J23.22 ; also on sheet 12 16 24 30
I2C_GP0_DAT_1V8: J23.24 ; also on sheet 12 16 24 30
I2C_GP1_CLK_3V3: R208.1 ; also on sheet 2 3 12 13 18 19 30
I2C_GP1_DAT_3V3: R210.1 ; also on sheet 2 3 12 13 18 19 30
LCD1_BKLT_PWM: J23.100 ; also on sheet 29
LCD_BIAS_EN: J23.88 R244.1 ; also on sheet 13
LCD_BL_EN: J23.8 ; also on sheet 29
LCD_BL_PWM: J23.10 ; also on sheet 29
LCD_EN: J23.62 R182.1 U15.2(A) ; also on sheet 29
LCD_RST_L: J23.12 R182.2 U15.4(Y)
LCD_TE: J23.14 ; also on sheet 29
NVSR_INT: R253.2 ; also on sheet 13
NVSR_INT_R: J23.98 R253.1
SNN_DIS_64: J23.64
SNN_DIS_82: J23.82
SNN_DIS_111: J23.111
SNN_DIS_113: J23.113
SNN_DIS_114: J23.114
SNN_DIS_116: J23.116
SNN_DIS_118: J23.118
SNN_DIS_120: J23.120
SNN_EN_VDD_BL: J23.84
SNN_TOUCH_SHDN: J23.46
SNN_U1000_P5: U15.5(NC)
SPI0_CLK: J23.38 ; also on sheet 29
SPI0_CS0: J23.44 ; also on sheet 29
SPI0_MISO: J23.40 ; also on sheet 29
SPI0_MOSI: J23.42 ; also on sheet 29
SPI2_CS0: J23.110 ; also on sheet 28
SPI2_MISO: J23.106 ; also on sheet 16 28
SPI2_MOSI: J23.108 ; also on sheet 16 28
SPI2_SCK: J23.104 ; also on sheet 16 28
TOUCH_CLK: R218.2 ; also on sheet 29
TOUCH_CLK_R: J23.50 R218.1
TOUCH_INT: J23.34 ; also on sheet 29
TOUCH_RST: J23.36 ; also on sheet 29

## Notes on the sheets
sheet 17
- A
- B
- C
- D
- E
- F
- G
- H
- DISPLAY CONNECTOR
- 1
- 1
- VCCY
- VCCA
- 2
- 2
- 1.8V LCD_RST_L: Install R (HEye)
- 3.3V LCD_RST_L: Install U1 (ST8)
- Assign for Touch screen controller
- Vih = 0.90V
- Vil = 0.50V
- 3
- 3
- Vih = 0.90V
- Vil = 0.50V
- 4
- 4
- NS
- Vih = 0.90V
- Vil = 0.50V
- NS
- 5
- 5
- NVIDIA CORPORATION
- 2701 SAN TOMAS EXPRESSWAY
- ASSEMBLY
- <ASSEMBLY_DESCRIPTION>
- SANTA CLARA, CA 95050, USA
- PAGE DETAIL
- DSI Connector
- NV_PN
- 600-82597-BASE-900
- ALL NVIDIA DESIGN SPECIFICATIONS, REFERENCE SPECIFICATIONS, REFERENCE BOARDS, FILES, DRAWINGS, DIAGNOSTICS, LISTS AND OTHER DOCUMENTS OR INFORMATION (TOGETHER AND SEPARATELY, 'MATERIALS') ARE BEING PROVIDED 'AS IS'. THE MATERIALS MAY
- CONTAIN KNOWN AND UNKNOWN VIOLATIONS OR DEVIATIONS OF INDUSTRY STANDARDS AND SPECIFICATIONS. NVIDIA MAKES NO WARRANTIES, EXPRESSED, IMPLIED, STATUTORY OR OTHERWISE WITH RESPECT TO THE MATERIALS OR OTHERWISE, AND EXPRESSLY DISCLAIMS ALL
- PCB REV
- P2597-C02
- PAGE
- 17 OF 34
- IMPLIED WARRANTIES INCLUDING, WITHOUT LIMITATION, THE WARRANTIES OF DESIGN, OF NONINFRINGEMENT, MERCHANTABILITY OR FITNESS FOR A PARTICULAR PURPOSE, OR ARISING FROM A COURSE OF DEALING, TRADE USAGE, TRADE PRACTICE, OR INDUSTRY STANDARDS.
- BOM REV
- A
- DATE
- 23-OCT-2017
- A
- B
- C
- D
- E
- F
- G
- H
